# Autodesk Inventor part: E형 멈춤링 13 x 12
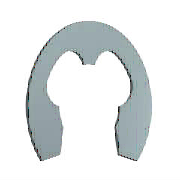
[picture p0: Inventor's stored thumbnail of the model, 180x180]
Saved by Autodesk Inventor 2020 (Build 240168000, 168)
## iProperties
Created: 2012-02
Part Number: E형 멈춤링 13 x 12
Material: 강철, 연강
Description: 스프링 리테이닝 링
Document SubType Name: Modeling
Standard: JIS B 2805
Designer: mdu-01
Standards Organization: JIS
Language: ko-KR
Size Designation: 12
Categories: <MemberInstance><Categories><Category DisplayName="샤프트 부품" InternalName="7f7aeb1f-a693-4053-b835-cee3144e0d98" Mnemonic="SHFT"><Category DisplayName="써클립" Inter
Density: 1 g/cm^3
Appearance: 강철(1)
IsCustomPart: 1
Author: mdu-01
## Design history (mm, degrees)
sketch "스케치1"
  geometry: L1 (-1.2, 0.024)-(0, 0.024) reference; L2 (-3.206, 0)-(3.486, 0) reference; L3 (-5.499, -8.876)-(5.499, -8.876); L4 (0, 1.949)-(0, -3.479) reference; L5 (-7.2, -4.076)-(-6.024, -4.076); L6 (-1.2, 0.724)-(-1.2, 1.889); L7 (0, 5.024)-(2.53, 5.024); L8 (-5.499, -8.876)-(-6.729, -11.985); L9 (0, -0.476)-(-1.278, -0.476); L10 (5.499, -8.876)-(6.729, -11.985); L11 (7.2, -4.076)-(6.024, -4.076); L12 (1.2, 0.724)-(1.2, 1.889); C1 r 6.5 at (0, -6.476); A1 r 6 centre (0, -6.476) between (-5.683, -4.552) and (-5.499, -8.876); A2 r 1.2 centre (0, 0.724) between (-1.2, 0.724) and (1.2, 0.724); A3 r 11.5 centre (0, -6.476) between (9.962, -12.222) and (-9.962, -12.222); A4 r 9.6 centre (0, -6.476) between (-2.4, 2.819) and (-8.471, -1.959); A5 r 0.96 centre (-2.16, 1.889) between (-1.2, 1.889) and (-2.4, 2.819); A6 r 1.44 centre (-7.2, -2.636) between (-8.471, -1.959) and (-7.2, -4.076); A7 r 0.36 centre (-6.024, -4.436) between (-5.683, -4.552) and (-6.024, -4.076); A8 r 1.8 centre (-8.403, -11.323) between (-9.962, -12.222) and (-6.729, -11.985); A9 r 1.8 centre (8.403, -11.323) between (6.729, -11.985) and (9.962, -12.222); A10 r 6 centre (0, -6.476) between (5.499, -8.876) and (5.683, -4.552); A11 r 0.36 centre (6.024, -4.436) between (6.024, -4.076) and (5.683, -4.552); A12 r 1.44 centre (7.2, -2.636) between (7.2, -4.076) and (8.471, -1.959); A13 r 9.6 centre (0, -6.476) between (8.471, -1.959) and (2.4, 2.819); A14 r 0.96 centre (2.16, 1.889) between (2.4, 2.819) and (1.2, 1.889); 1 further point
  constraints: 30 point on circle, 20 end point, 15 centre point, 13 symmetric about line, 12 tangent, 8 point on line, 4 parallel, 2 coincident, 2 horizontal, 1 concentric, 1 perpendicular, 1 vertical alignment, 9 other
  dimensions: "d0" = 13 diameter of C1 (= WD); "d3" = 2.4 distance from line of A1.centre L3 (= 0.2 x ND); "d4" = 1.2 radius of A2 (= 0.1 x ND); "d5" = 23 diameter of A3 (= SD2); "d8" = 9.6 radius of A4 (= 0.8 x ND); "d9" = 2.4 distance from line of A1.centre L5 (= 0.2 x ND); "d10" = 0.96 radius of A5 (= 0.08 x ND); "d11" = 1.44 radius of A6 (= 0.12 x ND); "d12" = 0.36 radius of A7 (= 0.03 x ND); "d13" = 1.8 radius of A8 (= 0.15 x ND); "d14" = 6 distance from line of A1.centre L9 (= 0.5 x ND); "d15" = 6 radius of A1 (= 0.5 x ND)
extrude "본체" new body sketch "스케치1" distance "d16" = 1 (= SD); taper "d17" = 0 deg
workaxis "Work Axis1"
workaxis "Work Axis2"
workplane "Work Plane1"
body "Solid1"
other parameters: "ND" = 12 [user parameter; used in 14 equation terms], "SD" = 1 [user parameter; used in 1 equation term], "WD" = 13 (= WDMIN) [user parameter; used in 1 equation term], "d1" = 19.2 (= 1.6 x ND), "d2" = 12 (= ND), "SD2" = 23 [user parameter; used in 1 equation term], "d6" = 12 (= ND), "d7" = 1.8 (= 0.15 x ND), "d18" = 0, "d19" = 0, "d27" = 0, "d28" = 0, "WDMIN" = 13 [user parameter; used in 1 equation term], "SNB" = 1.15 [user parameter], "WDMAX" = 18 [user parameter], "BUBRMI" = 2.5 [user parameter]
